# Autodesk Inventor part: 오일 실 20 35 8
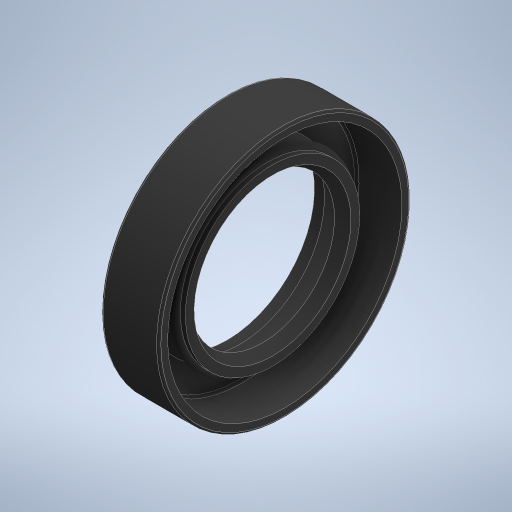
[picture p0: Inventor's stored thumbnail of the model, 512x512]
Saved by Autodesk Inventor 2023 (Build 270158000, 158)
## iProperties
Created: 2026-03
Part Number: 오일 실 20 35 8
Material: 고무
Description: 오일-실
Document SubType Name: Modeling
Designer: home
Density: 0.93 g/cm^3
Appearance: 기본값
Author: jhkim
Sending System: Autodesk Inventor 2026
Preprocessor: ST-DEVELOPER v20.1
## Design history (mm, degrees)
feature "Solid1"
node "솔리드1"
